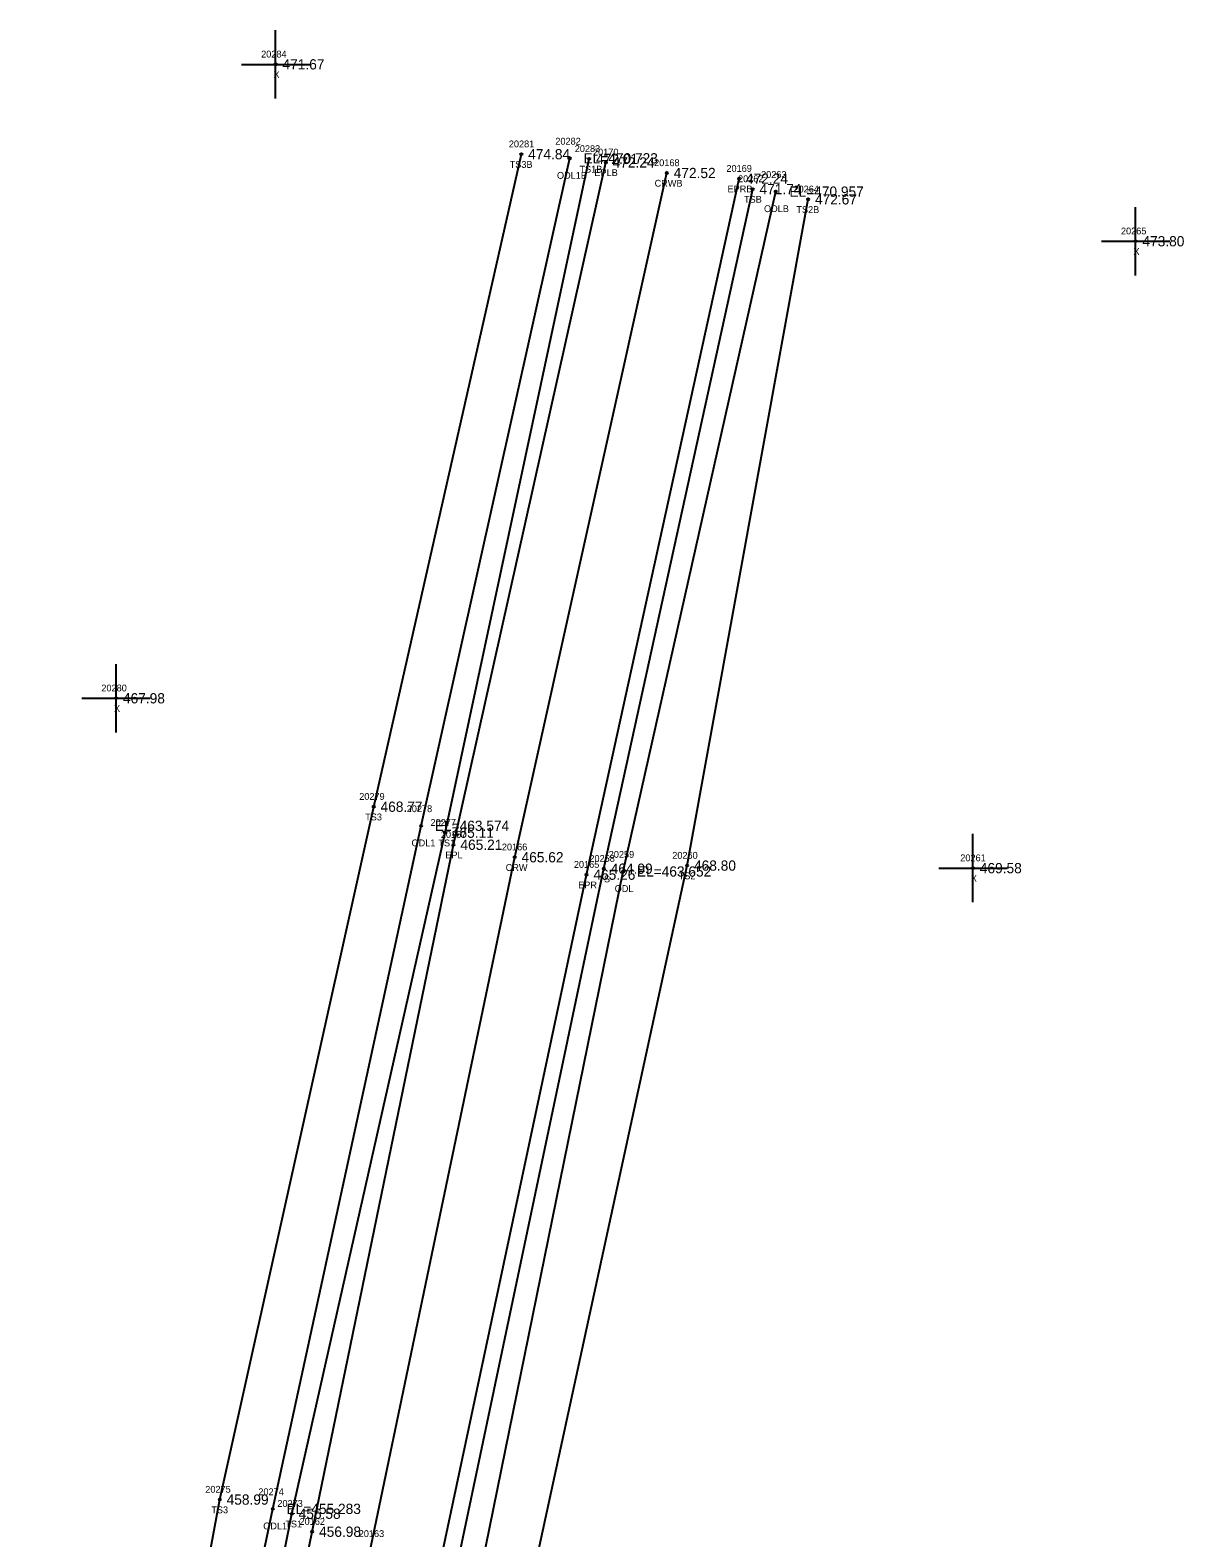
# Model space of a CAD drawing. Extents: x 1755707 to 1756750, y 975854 to 977363.
# Drawn here: x 1756264.8 to 1756433.5, y 977142.4 to 977362.9 of the extents above; entities that cross this region are included whole.
import ezdxf

# ---------------------------------------------------------------- set-up
doc = ezdxf.new("R2010")
doc.units = 0
for name, color, linetype in [('RD_DTM_BkLn1', 7, 'Continuous'), ('RD_DTM_BkLn2', 7, 'Continuous'), ('RD_DTM_BkLn_txCode', 7, 'Continuous'), ('RD_EX_H2O', 7, 'Continuous'), ('RD_EX_H2O_txCode', 7, 'Continuous'), ('RD_EX_Misc', 7, 'Continuous'), ('RD_EX_Misc_txCode', 7, 'Continuous'), ('RD_EX_Road', 7, 'Continuous'), ('RD_EX_Road_txCode', 7, 'Continuous'), ('RD_EX_TX_H2O_ELEV', 7, 'Continuous'), ('RD_EX_TX_Misc_ELEV', 7, 'Continuous'), ('RD_EX_TX_Road_ELEV', 7, 'Continuous'), ('RD_HC_Survey_ELEV', 7, 'Continuous'), ('RD_HC_Survey_txCode', 7, 'Continuous'), ('RD_SMD_Locator', 7, 'Continuous')]:
    doc.layers.add(name, color=color, linetype=linetype)

msp = doc.modelspace()

# ---------------------------------------------------------------- linework, layer by layer
at = {"layer": 'RD_DTM_BkLn1'}
msp.add_lwpolyline([(1756212.24, 976646.92), (1756233.31, 976744.58), (1756253.87, 976843.36), (1756274.18, 976942.87), (1756294.7, 977044.28), (1756314.7, 977141.54), (1756335.65, 977241.96), (1756357.9, 977342.03)], dxfattribs=at)
at = {"layer": 'RD_DTM_BkLn2'}
for points in [[(1756101.82, 976704.9), (1756150.92, 976716.16), (1756211.72, 976728.04), (1756216.23, 976737.89), (1756238.86, 976847.03), (1756261.79, 976945.44), (1756283.19, 977044.99), (1756303.06, 977145.95), (1756325.46, 977245.55), (1756346.55, 977344.09)], [(1756266.62, 977008.29), (1756273.79, 977046.99), (1756292.52, 977148.02), (1756315.03, 977249.35), (1756336.62, 977344.78)], [(1756284.92, 976917.44), (1756285.93, 976941.18), (1756306.83, 977042.12), (1756327.31, 977138.86), (1756348.69, 977240.29), (1756370.45, 977339.68)], [(1756284.92, 976917.44), (1756292.37, 976916.44), (1756302.16, 976939.65), (1756320.07, 977035.33), (1756338.4, 977137.17), (1756360.87, 977240.74), (1756378.56, 977338.18)]]:
    msp.add_lwpolyline(points, dxfattribs=at)
at = {"layer": 'RD_EX_H2O'}
for points in [[(1756266.62, 977008.29), (1756279.21, 977045.93), (1756300.28, 977146.66), (1756321.97, 977246.56), (1756343.71, 977344.18)], [(1756290.04, 976919.26), (1756290.71, 976940.13), (1756310.79, 977041.34), (1756330.83, 977138.26), (1756351.52, 977239.88), (1756373.82, 977339.31)]]:
    msp.add_lwpolyline(points, dxfattribs=at)
at = {"layer": 'RD_EX_Misc'}
for p, q in [((1756300.69, 977352.92), (1756300.69, 977362.92)), ((1756295.69, 977357.92), (1756305.69, 977357.92)), ((1756426.45, 977327.05), (1756426.45, 977337.05)), ((1756421.45, 977332.05), (1756431.45, 977332.05)), ((1756277.36, 977260.21), (1756277.36, 977270.21)), ((1756272.36, 977265.21), (1756282.36, 977265.21)), ((1756402.67, 977235.37), (1756402.67, 977245.37)), ((1756397.67, 977240.37), (1756407.67, 977240.37))]:
    msp.add_line(p, q, dxfattribs=at)
at = {"layer": 'RD_EX_Road'}
for points in [[(1756212.24, 976646.92), (1756202.87, 976648.96), (1756215.01, 976705.04), (1756220.09, 976730.75), (1756223.91, 976746.46), (1756244.6, 976844.81), (1756265.35, 976944.71), (1756286.1, 977045.83), (1756306.04, 977143.32), (1756326.71, 977243.79), (1756348.97, 977343.58)], [(1756212.24, 976646.92), (1756220.86, 976645.39), (1756242.73, 976741.74), (1756264.15, 976840.28), (1756284.31, 976940.54), (1756305.17, 977042.39), (1756325.03, 977140.07), (1756346.16, 977239.41), (1756368.47, 977341.2)]]:
    msp.add_lwpolyline(points, dxfattribs=at)
at = {"layer": 'RD_SMD_Locator'}
for centre in [(1756300.69, 977357.92), (1756336.62, 977344.78), (1756343.71, 977344.18), (1756346.55, 977344.09), (1756348.97, 977343.58), (1756357.9, 977342.03), (1756368.47, 977341.2), (1756370.45, 977339.68), (1756373.82, 977339.31), (1756378.56, 977338.18), (1756426.45, 977332.05), (1756277.36, 977265.21), (1756315.03, 977249.35), (1756321.97, 977246.56), (1756325.46, 977245.55), (1756326.71, 977243.79), (1756335.65, 977241.96), (1756346.16, 977239.41), (1756348.69, 977240.29), (1756351.52, 977239.88), (1756360.87, 977240.74), (1756402.67, 977240.37), (1756292.52, 977148.02), (1756300.28, 977146.66), (1756303.06, 977145.95), (1756306.04, 977143.32)]:
    msp.add_circle(centre, 0.15, dxfattribs=at)

# ---------------------------------------------------------------- texts
at = {"layer": 'RD_DTM_BkLn_txCode'}
for s, p in [('20281', (1756334.79, 977345.78)), ('20283', (1756344.43, 977345.09)), ('TS3B', (1756334.91, 977342.78)), ('TS1B', (1756345.12, 977342.09)), ('20262', (1756368.31, 977340.68)), ('TSB', (1756369.18, 977337.68)), ('20264', (1756376.42, 977339.18)), ('TS2B', (1756376.84, 977336.18)), ('20279', (1756312.91, 977250.35)), ('TS3', (1756313.78, 977247.35)), ('20277', (1756323.34, 977246.55)), ('TS1', (1756324.49, 977243.55)), ('20258', (1756346.57, 977241.29)), ('20260', (1756358.69, 977241.74)), ('TS', (1756347.89, 977238.29)), ('TS2', (1756359.63, 977238.74)), ('20275', (1756290.4, 977149.02)), ('TS3', (1756291.28, 977146.02)), ('20273', (1756300.94, 977146.95)), ('TS1', (1756302.1, 977143.95))]:
    msp.add_text(s, height=1, dxfattribs=at).set_placement(p)
at = {"layer": 'RD_EX_H2O_txCode'}
for s, p in [('20282', (1756341.59, 977346.18)), ('ODL1B', (1756341.83, 977341.18)), ('20263', (1756371.68, 977341.31)), ('ODLB', (1756372.11, 977336.31)), ('20278', (1756319.86, 977248.56)), ('ODL1', (1756320.56, 977243.56)), ('20259', (1756349.4, 977241.88)), ('ODL', (1756350.27, 977236.88)), ('20274', (1756298.16, 977148.66)), ('ODL1', (1756298.87, 977143.66))]:
    msp.add_text(s, height=1, dxfattribs=at).set_placement(p)
at = {"layer": 'RD_EX_Misc_txCode'}
for s, p in [('20284', (1756298.57, 977358.92)), ('X', (1756300.37, 977355.92)), ('20265', (1756424.31, 977333.05)), ('X', (1756426.13, 977330.05)), ('20280', (1756275.2, 977266.21)), ('X', (1756277.05, 977263.21)), ('20261', (1756400.81, 977241.37)), ('X', (1756402.36, 977238.37))]:
    msp.add_text(s, height=1, dxfattribs=at).set_placement(p)
at = {"layer": 'RD_EX_Road_txCode'}
for s, p in [('20170', (1756347.1, 977344.58)), ('20169', (1756366.61, 977342.2)), ('EPLB', (1756347.3, 977341.58)), ('EPRB', (1756366.77, 977339.2)), ('20167', (1756324.85, 977244.79)), ('EPL', (1756325.5, 977241.79)), ('20165', (1756344.3, 977240.41)), ('EPR', (1756344.93, 977237.41)), ('20162', (1756304.18, 977144.32))]:
    msp.add_text(s, height=1, dxfattribs=at).set_placement(p)
at = {"layer": 'RD_EX_TX_H2O_ELEV'}
for s, p in [('EL=470.723', (1756345.71, 977343.43)), ('EL=470.957', (1756375.82, 977338.56)), ('EL=463.574', (1756323.97, 977245.81)), ('EL=463.652', (1756353.52, 977239.13)), ('EL=455.283', (1756302.28, 977145.91))]:
    msp.add_text(s, height=1.5, dxfattribs=at).set_placement(p)
at = {"layer": 'RD_EX_TX_Misc_ELEV'}
for s, p in [('471.67', (1756301.69, 977357.17)), ('474.84', (1756337.62, 977344.03)), ('472.01', (1756347.55, 977343.34)), ('471.74', (1756371.45, 977338.93)), ('472.67', (1756379.56, 977337.43)), ('473.80', (1756427.45, 977331.3)), ('467.98', (1756278.36, 977264.46)), ('468.77', (1756316.03, 977248.6)), ('465.11', (1756326.46, 977244.8)), ('468.80', (1756361.87, 977239.99)), ('464.99', (1756349.69, 977239.54)), ('469.58', (1756403.67, 977239.62)), ('458.99', (1756293.52, 977147.27)), ('456.58', (1756304.06, 977145.2))]:
    msp.add_text(s, height=1.5, dxfattribs=at).set_placement(p)
at = {"layer": 'RD_EX_TX_Road_ELEV'}
for s, p in [('472.24', (1756349.97, 977342.83)), ('472.24', (1756369.47, 977340.45)), ('465.21', (1756327.71, 977243.04)), ('465.26', (1756347.16, 977238.66)), ('456.98', (1756307.04, 977142.57))]:
    msp.add_text(s, height=1.5, dxfattribs=at).set_placement(p)
at = {"layer": 'RD_HC_Survey_ELEV'}
for s, p in [('472.52', (1756358.9, 977341.28)), ('465.62', (1756336.65, 977241.21))]:
    msp.add_text(s, height=1.5, dxfattribs=at).set_placement(p)
at = {"layer": 'RD_HC_Survey_txCode'}
for s, p in [('20168', (1756356.04, 977343.03)), ('CRWB', (1756356.11, 977340.03)), ('20166', (1756333.77, 977242.96)), ('CRW', (1756334.33, 977239.96)), ('20163', (1756312.84, 977142.54))]:
    msp.add_text(s, height=1, dxfattribs=at).set_placement(p)

doc.saveas('drawing.dxf')
